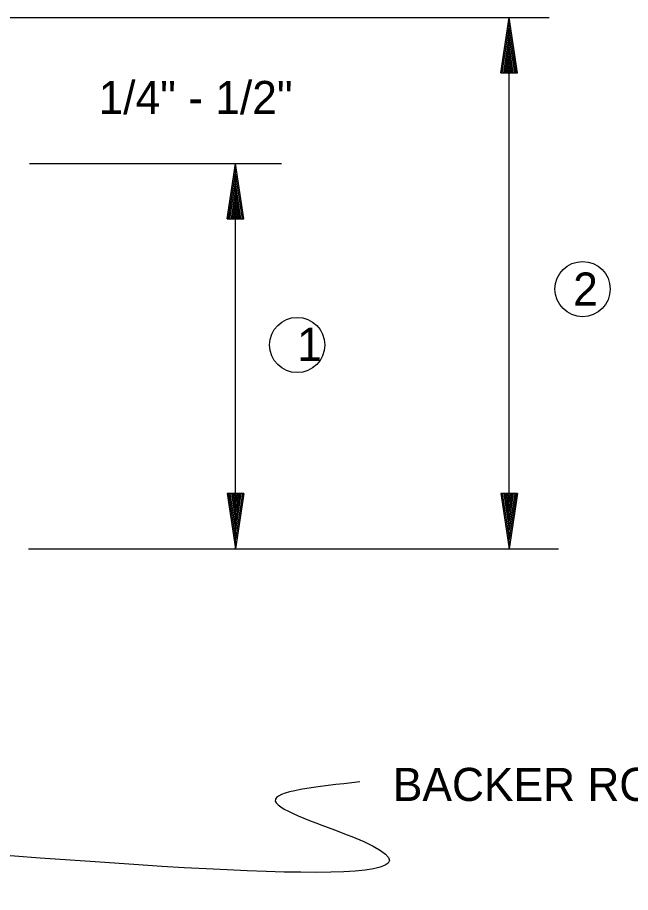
# Model space of a CAD drawing. Extents: x 1375738 to 1375905, y 380661 to 380875.
# Drawn here: x 1375782.84 to 1375793.93, y 380705.3 to 380721.15 of the extents above; entities that cross this region are included whole.
import ezdxf

# ---------------------------------------------------------------- set-up
doc = ezdxf.new("R2010")
doc.units = 0
doc.layers.add('R_Draft', color=7, linetype='Continuous')

msp = doc.modelspace()

# ---------------------------------------------------------------- linework, layer by layer
at = {"layer": 'R_Draft'}
for p, q in [((1375782.58, 380721.147), (1375792.462, 380721.147)), ((1375791.588, 380720.147), (1375791.738, 380721.147)), ((1375791.738, 380711.525), (1375791.738, 380721.147)), ((1375791.888, 380720.147), (1375791.738, 380721.147)), ((1375791.613, 380720.147), (1375791.738, 380720.98)), ((1375791.863, 380720.147), (1375791.738, 380720.98)), ((1375791.639, 380720.147), (1375791.738, 380720.808)), ((1375791.838, 380720.147), (1375791.738, 380720.808)), ((1375791.664, 380720.147), (1375791.738, 380720.642)), ((1375791.813, 380720.147), (1375791.738, 380720.642)), ((1375791.69, 380720.147), (1375791.738, 380720.472)), ((1375791.787, 380720.147), (1375791.738, 380720.472)), ((1375791.715, 380720.147), (1375791.738, 380720.305)), ((1375791.762, 380720.147), (1375791.738, 380720.305)), ((1375791.588, 380720.147), (1375791.888, 380720.147)), ((1375783.052, 380718.5), (1375787.618, 380718.5)), ((1375786.632, 380717.5), (1375786.782, 380718.5)), ((1375786.782, 380711.525), (1375786.782, 380718.5)), ((1375786.932, 380717.5), (1375786.782, 380718.5)), ((1375786.657, 380717.5), (1375786.782, 380718.333)), ((1375786.907, 380717.5), (1375786.782, 380718.333)), ((1375786.683, 380717.5), (1375786.782, 380718.161)), ((1375786.882, 380717.5), (1375786.782, 380718.161)), ((1375786.708, 380717.5), (1375786.782, 380717.994)), ((1375786.857, 380717.5), (1375786.782, 380717.994)), ((1375786.734, 380717.5), (1375786.782, 380717.825)), ((1375786.831, 380717.5), (1375786.782, 380717.825)), ((1375786.759, 380717.5), (1375786.782, 380717.658)), ((1375786.806, 380717.5), (1375786.782, 380717.658)), ((1375786.632, 380717.5), (1375786.932, 380717.5)), ((1375786.632, 380712.525), (1375786.782, 380711.525)), ((1375786.932, 380712.525), (1375786.632, 380712.525)), ((1375786.657, 380712.525), (1375786.782, 380711.692)), ((1375786.683, 380712.525), (1375786.782, 380711.864)), ((1375786.708, 380712.525), (1375786.782, 380712.031)), ((1375786.733, 380712.525), (1375786.782, 380712.2)), ((1375786.759, 380712.525), (1375786.782, 380712.367)), ((1375786.932, 380712.525), (1375786.782, 380711.525)), ((1375786.831, 380712.525), (1375786.782, 380712.2)), ((1375786.882, 380712.525), (1375786.782, 380711.864)), ((1375786.907, 380712.525), (1375786.782, 380711.692)), ((1375786.857, 380712.525), (1375786.782, 380712.031)), ((1375786.806, 380712.525), (1375786.782, 380712.367)), ((1375791.588, 380712.525), (1375791.738, 380711.525)), ((1375791.888, 380712.525), (1375791.588, 380712.525)), ((1375791.613, 380712.525), (1375791.738, 380711.692)), ((1375791.639, 380712.525), (1375791.738, 380711.864)), ((1375791.664, 380712.525), (1375791.738, 380712.031)), ((1375791.689, 380712.525), (1375791.738, 380712.2)), ((1375791.715, 380712.525), (1375791.738, 380712.367)), ((1375791.888, 380712.525), (1375791.738, 380711.525)), ((1375791.787, 380712.525), (1375791.738, 380712.2)), ((1375791.838, 380712.525), (1375791.738, 380711.864)), ((1375791.863, 380712.525), (1375791.738, 380711.692)), ((1375791.813, 380712.525), (1375791.738, 380712.031)), ((1375791.762, 380712.525), (1375791.738, 380712.367)), ((1375783.038, 380711.525), (1375792.629, 380711.525))]:
    msp.add_line(p, q, dxfattribs=at)
for centre in [(1375793.067, 380716.228), (1375787.9, 380715.215)]:
    msp.add_circle(centre, 0.5, dxfattribs=at)
msp.add_spline([(1375789.037, 380707.299), (1375787.504, 380706.953), (1375788.889, 380706.31), (1375781.373, 380706.063)], degree=3, dxfattribs=at)

# ---------------------------------------------------------------- texts
for s, p in [('1/4" - 1/2"', (1375784.304, 380719.398)), ('2', (1375792.897, 380715.928)), ('1', (1375787.9, 380714.927)), ('BACKER ROD', (1375789.632, 380706.955))]:
    msp.add_text(s, height=0.6, dxfattribs=at).set_placement(p)

doc.saveas('drawing.dxf')
